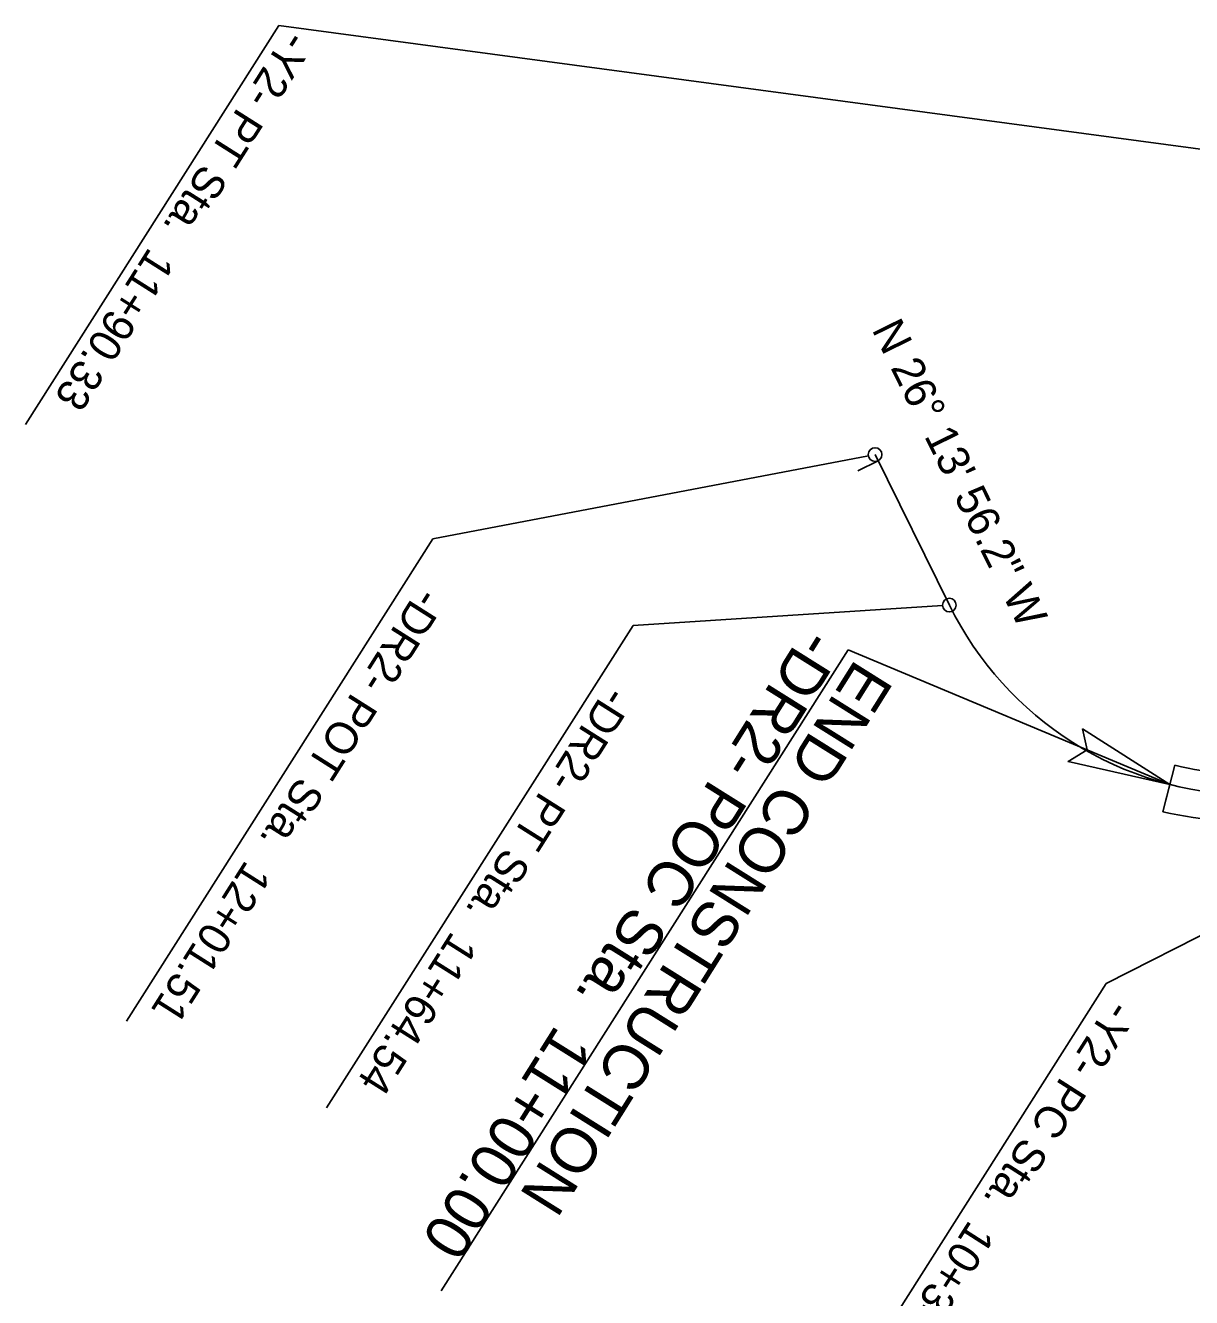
# Model space of a CAD drawing. Extents: x 1778969 to 1790720, y 807089 to 817794.
# Drawn here: x 1780657.2 to 1780913.9, y 812006.4 to 812286.5 of the extents above; entities that cross this region are included whole.
import ezdxf

# ---------------------------------------------------------------- set-up
doc = ezdxf.new("R2010")
doc.units = 0
for name, color, linetype in [('Prop EOT', 7, 'Continuous'), ('Prop Horizontal Alignment', 7, 'Continuous'), ('Prop Horizontal Alignment Direction Label', 7, 'Continuous'), ('Prop Horizontal Alignment Station Label', 7, 'Continuous'), ('Prop Horizontal Alignment Tick Small', 7, 'Continuous'), ('Prop Terminator CELL', 7, 'Continuous')]:
    doc.layers.add(name, color=color, linetype=linetype)

msp = doc.modelspace()

# ---------------------------------------------------------------- linework, layer by layer
at = {"layer": 'Prop EOT'}
msp.add_line((1780907.55, 812113.38), (1780910.2, 812123.63), dxfattribs=at)
for centre, radius, start, end in [((1780926.89, 812191.94), 70.32, 256.2726, 294.4698), ((1780926, 812191.87), 80.62, 256.7781, 294.9753)]:
    msp.add_arc(centre, radius, start, end, dxfattribs=at)
at = {"layer": 'Prop Horizontal Alignment'}
msp.add_line((1780860.56, 812158.87), (1780844.22, 812192.03), dxfattribs=at)
msp.add_arc((1780927.84, 812192.02), 75, 206.2323, 331.9308, dxfattribs=at)
at = {"layer": 'Prop Horizontal Alignment Station Label'}
for p, q in [((1780712.98, 812286.51), (1780657.22, 812198.64)), ((1780933.98, 812256.79), (1780712.98, 812286.51)), ((1780842.75, 812191.75), (1780746.85, 812173.5)), ((1780746.85, 812173.5), (1780679.42, 812067.24)), ((1780859.07, 812158.77), (1780790.93, 812154.42)), ((1780790.93, 812154.42), (1780723.5, 812048.16)), ((1780838.28, 812149.04), (1780748.71, 812007.9)), ((1780838.28, 812149.04), (1780909.11, 812119.39)), ((1781025.18, 812141.72), (1780895.08, 812075.57)), ((1780895.08, 812075.57), (1780836.52, 811983.29))]:
    msp.add_line(p, q, dxfattribs=at)
for centre in [(1780844.22, 812192.03), (1780860.56, 812158.87)]:
    msp.add_circle(centre, 1.5, dxfattribs=at)
at = {"layer": 'Prop Horizontal Alignment Tick Small'}
for p, q in [((1780844.89, 812190.68), (1780840.4, 812188.47)), ((1780909.11, 812119.39), (1780907.86, 812114.55))]:
    msp.add_line(p, q, dxfattribs=at)
at = {"layer": 'Prop Terminator CELL'}
msp.add_lwpolyline([(1780889.85, 812131.66), (1780909.11, 812119.39), (1780886.69, 812124.44), (1780890.89, 812127.02)], close=True, dxfattribs=at)

# ---------------------------------------------------------------- texts
at = {"layer": 'Prop Horizontal Alignment Direction Label'}
msp.add_text('N 26%%d 13\' 56.2" W', height=7, rotation=296.2323, dxfattribs=at).set_placement((1780843.38, 812219.59))
at = {"layer": 'Prop Horizontal Alignment Station Label'}
for s, height, rotation, p in [('-Y2- PT Sta.  11+90.33', 7, 237.6454, (1780714.81, 812285.79)), ('-DR2- POT Sta.  12+01.51', 7, 237.6303, (1780743.87, 812163.14)), ('-DR2- POC Sta.  11+00.00', 10, 237.8988, (1780828.87, 812154.24)), ('END CONSTRUCTION', 10, 237.8988, (1780839.97, 812147.28)), ('-DR2- PT Sta.  11+64.54', 7, 237.7258, (1780785.25, 812141.41)), ('-Y2- PC Sta.  10+34.03', 7, 237.407, (1780896.1, 812072.34))]:
    msp.add_text(s, height=height, rotation=rotation, dxfattribs=at).set_placement(p)

doc.saveas('drawing.dxf')
